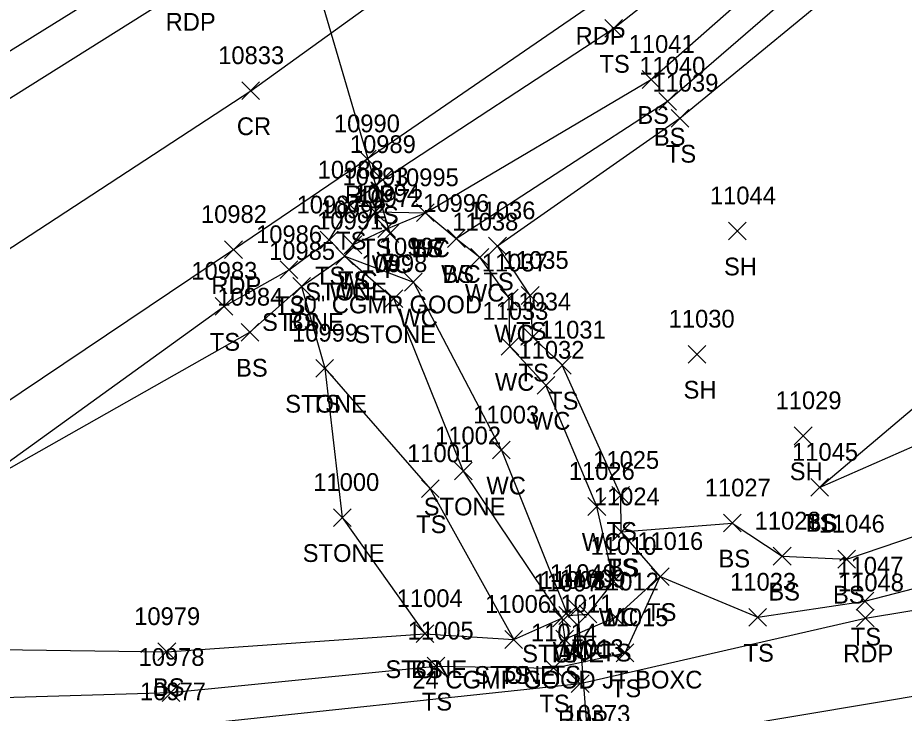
# Model space of a CAD drawing. Extents: x 1475671 to 1477951, y 592661 to 593821.
# Drawn here: x 1476588.2 to 1476688.2, y 593075.6 to 593153.9 of the extents above; entities that cross this region are included whole.
import ezdxf

# ---------------------------------------------------------------- set-up
doc = ezdxf.new("R2010")
doc.units = 0
for name, color, linetype in [('D_A', 7, 'Continuous'), ('D_C', 7, 'Continuous'), ('D_I', 7, 'Continuous'), ('D_TIC', 7, 'Continuous'), ('DCP', 7, 'Continuous'), ('L_A', 7, 'Continuous'), ('L_I', 7, 'Continuous'), ('L_TIC', 7, 'Continuous'), ('LASF', 7, 'Continuous'), ('LAWE', 7, 'Continuous'), ('LELB', 7, 'Continuous'), ('P_A', 7, 'Continuous'), ('P_I', 7, 'Continuous'), ('P_TIC', 7, 'Continuous'), ('PET', 7, 'Continuous'), ('PRC', 7, 'Continuous')]:
    doc.layers.add(name, color=color, linetype=linetype)

msp = doc.modelspace()

# ---------------------------------------------------------------- linework, layer by layer
at = {"layer": 'D_TIC'}
for points in [[(1476629.198, 593128.602), (1476631.198, 593130.602)], [(1476631.198, 593128.602), (1476629.198, 593130.602)], [(1476650.343, 593086.34), (1476652.343, 593088.34)], [(1476652.343, 593086.34), (1476650.343, 593088.34)]]:
    msp.add_lwpolyline(points, dxfattribs=at)
at = {"layer": 'DCP'}
for points in [[(1476616.882, 593174.886), (1476630.198, 593129.602)], [(1476651.343, 593087.34), (1476653.654, 593058.021)]]:
    msp.add_lwpolyline(points, dxfattribs=at)
at = {"layer": 'L_TIC'}
for points in [[(1476654.414, 593151.716), (1476656.414, 593153.716)], [(1476656.414, 593151.716), (1476654.414, 593153.716)], [(1476658.654, 593145.953), (1476660.654, 593147.953)], [(1476660.654, 593145.953), (1476658.654, 593147.953)], [(1476660.509, 593143.505), (1476662.509, 593145.505)], [(1476662.509, 593143.505), (1476660.509, 593145.505)], [(1476661.901, 593141.587), (1476663.901, 593143.587)], [(1476663.901, 593141.587), (1476661.901, 593143.587)], [(1476628.363, 593134.667), (1476630.363, 593136.667)], [(1476630.363, 593134.667), (1476628.363, 593136.667)], [(1476624.724, 593131.792), (1476626.724, 593133.792)], [(1476626.724, 593131.792), (1476624.724, 593133.792)], [(1476627.529, 593131.031), (1476629.529, 593133.031)], [(1476629.529, 593131.031), (1476627.529, 593133.031)], [(1476633.196, 593130.937), (1476635.196, 593132.937)], [(1476635.196, 593130.937), (1476633.196, 593132.937)], [(1476633.196, 593130.937), (1476635.196, 593132.937)], [(1476635.196, 593130.937), (1476633.196, 593132.937)], [(1476633.196, 593130.937), (1476635.196, 593132.937)], [(1476635.196, 593130.937), (1476633.196, 593132.937)], [(1476628.839, 593129.141), (1476630.839, 593131.141)], [(1476630.839, 593129.141), (1476628.839, 593131.141)], [(1476668.378, 593128.885), (1476670.378, 593130.885)], [(1476670.378, 593128.885), (1476668.378, 593130.885)], [(1476622.348, 593127.862), (1476624.348, 593129.862)], [(1476624.348, 593127.862), (1476622.348, 593129.862)], [(1476625.038, 593127.324), (1476627.038, 593129.324)], [(1476627.038, 593127.324), (1476625.038, 593129.324)], [(1476625.038, 593127.324), (1476627.038, 593129.324)], [(1476627.038, 593127.324), (1476625.038, 593129.324)], [(1476636.677, 593128.038), (1476638.677, 593130.038)], [(1476638.677, 593128.038), (1476636.677, 593130.038)], [(1476636.677, 593128.038), (1476638.677, 593130.038)], [(1476638.677, 593128.038), (1476636.677, 593130.038)], [(1476641.326, 593127.206), (1476643.326, 593129.206)], [(1476643.326, 593127.206), (1476641.326, 593129.206)], [(1476624.1, 593126.06), (1476626.1, 593128.06)], [(1476626.1, 593126.06), (1476624.1, 593128.06)], [(1476624.1, 593126.06), (1476626.1, 593128.06)], [(1476626.1, 593126.06), (1476624.1, 593128.06)], [(1476624.1, 593126.06), (1476626.1, 593128.06)], [(1476626.1, 593126.06), (1476624.1, 593128.06)], [(1476639.338, 593125.932), (1476641.338, 593127.932)], [(1476641.338, 593125.932), (1476639.338, 593127.932)], [(1476639.338, 593125.932), (1476641.338, 593127.932)], [(1476641.338, 593125.932), (1476639.338, 593127.932)], [(1476617.836, 593124.518), (1476619.836, 593126.518)], [(1476619.836, 593124.518), (1476617.836, 593126.518)], [(1476619.244, 593122.636), (1476621.244, 593124.636)], [(1476621.244, 593122.636), (1476619.244, 593124.636)], [(1476619.244, 593122.636), (1476621.244, 593124.636)], [(1476621.244, 593122.636), (1476619.244, 593124.636)], [(1476619.244, 593122.636), (1476621.244, 593124.636)], [(1476621.244, 593122.636), (1476619.244, 593124.636)], [(1476631.844, 593123.124), (1476633.844, 593125.124)], [(1476633.844, 593123.124), (1476631.844, 593125.124)], [(1476629.644, 593121.248), (1476631.644, 593123.248)], [(1476631.644, 593121.248), (1476629.644, 593123.248)], [(1476642.649, 593121.325), (1476644.649, 593123.325)], [(1476644.649, 593121.325), (1476642.649, 593123.325)], [(1476645.015, 593121.62), (1476647.015, 593123.62)], [(1476647.015, 593121.62), (1476645.015, 593123.62)], [(1476610.484, 593120.393), (1476612.484, 593122.393)], [(1476612.484, 593120.393), (1476610.484, 593122.393)], [(1476613.413, 593117.476), (1476615.413, 593119.476)], [(1476615.413, 593117.476), (1476613.413, 593119.476)], [(1476645.295, 593116.931), (1476647.295, 593118.931)], [(1476647.295, 593116.931), (1476645.295, 593118.931)], [(1476642.724, 593115.881), (1476644.724, 593117.881)], [(1476644.724, 593115.881), (1476642.724, 593117.881)], [(1476663.813, 593115.002), (1476665.813, 593117.002)], [(1476665.813, 593115.002), (1476663.813, 593117.002)], [(1476621.849, 593113.421), (1476623.849, 593115.421)], [(1476623.849, 593113.421), (1476621.849, 593115.421)], [(1476621.849, 593113.421), (1476623.849, 593115.421)], [(1476623.849, 593113.421), (1476621.849, 593115.421)], [(1476648.631, 593113.766), (1476650.631, 593115.766)], [(1476650.631, 593113.766), (1476648.631, 593115.766)], [(1476646.792, 593111.499), (1476648.792, 593113.499)], [(1476648.792, 593111.499), (1476646.792, 593113.499)], [(1476675.786, 593105.811), (1476677.786, 593107.811)], [(1476677.786, 593105.811), (1476675.786, 593107.811)], [(1476641.768, 593104.199), (1476643.768, 593106.199)], [(1476643.768, 593104.199), (1476641.768, 593106.199)], [(1476637.472, 593101.841), (1476639.472, 593103.841)], [(1476639.472, 593101.841), (1476637.472, 593103.841)], [(1476633.755, 593099.845), (1476635.755, 593101.845)], [(1476635.755, 593099.845), (1476633.755, 593101.845)], [(1476677.643, 593099.996), (1476679.643, 593101.996)], [(1476679.643, 593099.996), (1476677.643, 593101.996)], [(1476677.643, 593099.996), (1476679.643, 593101.996)], [(1476679.643, 593099.996), (1476677.643, 593101.996)], [(1476655.219, 593099.091), (1476657.219, 593101.091)], [(1476657.219, 593099.091), (1476655.219, 593101.091)], [(1476655.219, 593099.091), (1476657.219, 593101.091)], [(1476657.219, 593099.091), (1476655.219, 593101.091)], [(1476652.527, 593097.843), (1476654.527, 593099.843)], [(1476654.527, 593097.843), (1476652.527, 593099.843)], [(1476623.828, 593096.599), (1476625.828, 593098.599)], [(1476625.828, 593096.599), (1476623.828, 593098.599)], [(1476667.799, 593095.978), (1476669.799, 593097.978)], [(1476669.799, 593095.978), (1476667.799, 593097.978)], [(1476655.284, 593094.976), (1476657.284, 593096.976)], [(1476657.284, 593094.976), (1476655.284, 593096.976)], [(1476655.284, 593094.976), (1476657.284, 593096.976)], [(1476657.284, 593094.976), (1476655.284, 593096.976)], [(1476673.422, 593092.252), (1476675.422, 593094.252)], [(1476675.422, 593092.252), (1476673.422, 593094.252)], [(1476680.706, 593091.914), (1476682.706, 593093.914)], [(1476682.706, 593091.914), (1476680.706, 593093.914)], [(1476654.436, 593089.406), (1476656.436, 593091.406)], [(1476656.436, 593089.406), (1476654.436, 593091.406)], [(1476659.671, 593089.953), (1476661.671, 593091.953)], [(1476661.671, 593089.953), (1476659.671, 593091.953)], [(1476659.671, 593089.953), (1476661.671, 593091.953)], [(1476661.671, 593089.953), (1476659.671, 593091.953)], [(1476682.751, 593087.182), (1476684.751, 593089.182)], [(1476684.751, 593087.182), (1476682.751, 593089.182)], [(1476648.567, 593085.274), (1476650.567, 593087.274)], [(1476650.567, 593085.274), (1476648.567, 593087.274)], [(1476648.567, 593085.274), (1476650.567, 593087.274)], [(1476650.567, 593085.274), (1476648.567, 593087.274)], [(1476648.567, 593085.274), (1476650.567, 593087.274)], [(1476650.567, 593085.274), (1476648.567, 593087.274)], [(1476649.26, 593085.567), (1476651.26, 593087.567)], [(1476651.26, 593085.567), (1476649.26, 593087.567)], [(1476651.52, 593085.726), (1476653.52, 593087.726)], [(1476653.52, 593085.726), (1476651.52, 593087.726)], [(1476654.619, 593085.384), (1476656.619, 593087.384)], [(1476656.619, 593085.384), (1476654.619, 593087.384)], [(1476670.661, 593085.365), (1476672.661, 593087.365)], [(1476672.661, 593085.365), (1476670.661, 593087.365)], [(1476633.151, 593083.513), (1476635.151, 593085.513)], [(1476635.151, 593083.513), (1476633.151, 593085.513)], [(1476633.151, 593083.513), (1476635.151, 593085.513)], [(1476635.151, 593083.513), (1476633.151, 593085.513)], [(1476643.161, 593082.865), (1476645.161, 593084.865)], [(1476645.161, 593082.865), (1476643.161, 593084.865)], [(1476643.161, 593082.865), (1476645.161, 593084.865)], [(1476645.161, 593082.865), (1476643.161, 593084.865)], [(1476648.912, 593082.903), (1476650.912, 593084.903)], [(1476650.912, 593082.903), (1476648.912, 593084.903)], [(1476604.047, 593081.486), (1476606.047, 593083.486)], [(1476606.047, 593081.486), (1476604.047, 593083.486)], [(1476655.704, 593081.361), (1476657.704, 593083.361)], [(1476657.704, 593081.361), (1476655.704, 593083.361)], [(1476634.384, 593079.856), (1476636.384, 593081.856)], [(1476636.384, 593079.856), (1476634.384, 593081.856)], [(1476647.642, 593079.648), (1476649.642, 593081.648)], [(1476649.642, 593079.648), (1476647.642, 593081.648)], [(1476604.53, 593076.889), (1476606.53, 593078.889)], [(1476606.53, 593076.889), (1476604.53, 593078.889)]]:
    msp.add_lwpolyline(points, dxfattribs=at)
at = {"layer": 'LASF'}
for points in [[(1476620.244, 593123.636), (1476625.1, 593127.06), (1476630.644, 593122.248), (1476638.472, 593102.841), (1476649.567, 593086.274)], [(1476620.244, 593123.636), (1476622.849, 593114.421), (1476624.828, 593097.599), (1476634.151, 593084.513), (1476644.161, 593083.865), (1476649.567, 593086.274)]]:
    msp.add_lwpolyline(points, dxfattribs=at)
at = {"layer": 'LAWE'}
for points in [[(1476625.1, 593127.06), (1476626.038, 593128.324), (1476629.839, 593130.141), (1476634.196, 593131.937), (1476637.677, 593129.038), (1476640.338, 593126.932)], [(1476625.1, 593127.06), (1476632.844, 593124.124), (1476642.768, 593105.199), (1476650.26, 593086.567), (1476652.52, 593086.726), (1476655.436, 593090.406), (1476653.527, 593098.843), (1476647.792, 593112.499), (1476643.724, 593116.881), (1476643.649, 593122.325), (1476640.338, 593126.932)]]:
    msp.add_lwpolyline(points, dxfattribs=at)
at = {"layer": 'LELB'}
for points in [[(1476525.71, 593116.601), (1476535.993, 593117.469), (1476564.386, 593135.958), (1476604.974, 593161.161), (1476624.83, 593173.855), (1476638.095, 593183.34), (1476660.789, 593199.46), (1476676.812, 593212.322), (1476707.127, 593238.69), (1476723.806, 593252.602), (1476754.144, 593278.445), (1476785.314, 593303.015), (1476812.795, 593326.193), (1476842.986, 593352.592), (1476863.072, 593369.432), (1476886.56, 593389.771), (1476893.658, 593396.85), (1476901.202, 593401.682), (1476921.171, 593422.2)], [(1476564.119, 593090.41), (1476582.109, 593100.232), (1476611.484, 593121.393), (1476618.836, 593125.518), (1476623.348, 593128.862), (1476625.724, 593132.792), (1476629.363, 593135.667), (1476655.414, 593152.716), (1476679.208, 593171.494), (1476707.001, 593193.967), (1476724.55, 593208.697), (1476750.977, 593231.694), (1476770.543, 593248.256), (1476798.665, 593272.173), (1476825.817, 593296.201), (1476846.601, 593313.128), (1476851.351, 593312.899), (1476856.135, 593310.718)], [(1476634.196, 593131.937), (1476659.654, 593146.953), (1476682.124, 593166.734), (1476708.671, 593192.239), (1476725.714, 593207.355), (1476752.229, 593229.936), (1476771.816, 593246.254), (1476799.288, 593271.002), (1476827.809, 593293.853), (1476847.078, 593308.339), (1476849.309, 593306.853)], [(1476637.677, 593129.038), (1476661.509, 593144.505), (1476683.495, 593163.513), (1476710.241, 593189.501), (1476727.499, 593204.939), (1476753.67, 593228.482), (1476773.331, 593243.799), (1476800.693, 593269.416), (1476829.365, 593291.343), (1476849.309, 593306.853)], [(1476656.284, 593095.976), (1476668.799, 593096.978), (1476674.422, 593093.252), (1476681.706, 593092.914), (1476715.012, 593104.198), (1476743.407, 593111.461), (1476771.495, 593107.276), (1476782.768, 593105.348), (1476795.281, 593099.965), (1476811.259, 593100.054), (1476809.565, 593119.113), (1476813.359, 593153.775), (1476804.907, 593159.056), (1476804.556, 593163.805), (1476803.63, 593168.615), (1476810.963, 593186.977), (1476819.408, 593209.797), (1476828.138, 593245.308), (1476843.633, 593278.61), (1476845.713, 593295.921), (1476849.309, 593306.853)], [(1476678.643, 593100.996), (1476705.615, 593123.798), (1476726.041, 593155.108), (1476737.723, 593186.361), (1476761.68, 593213.282), (1476787.873, 593223.87), (1476810.461, 593252.94), (1476833.913, 593283.757), (1476845.713, 593295.921)], [(1476656.219, 593100.091), (1476649.631, 593114.766), (1476646.295, 593117.931), (1476646.015, 593122.62), (1476642.326, 593128.206), (1476662.901, 593142.587), (1476684.96, 593160.732), (1476712.646, 593184.752), (1476728.902, 593202.646), (1476756.289, 593223.253), (1476776.283, 593240.544), (1476803.274, 593265.829), (1476831.654, 593287.608)], [(1476678.643, 593100.996), (1476711.001, 593115.173), (1476731.223, 593143.421), (1476747.615, 593171.009), (1476767.456, 593198.639), (1476796.546, 593210.231), (1476815.094, 593241.804), (1476843.633, 593278.61)], [(1476626.038, 593128.324), (1476628.529, 593132.031), (1476634.196, 593131.937)], [(1476582.109, 593100.232), (1476614.413, 593118.476), (1476620.244, 593123.636)], [(1476622.849, 593114.421), (1476634.755, 593100.845), (1476644.161, 593083.865)], [(1476564.119, 593090.41), (1476564.346, 593083.027), (1476564.937, 593076.683), (1476605.53, 593077.889), (1476635.384, 593080.856), (1476648.642, 593080.648), (1476656.704, 593082.361), (1476660.671, 593090.953), (1476671.661, 593086.365), (1476683.751, 593088.182), (1476716.338, 593096.606), (1476747.988, 593101.226)], [(1476649.567, 593086.274), (1476649.912, 593083.903), (1476655.619, 593086.384), (1476660.671, 593090.953), (1476656.284, 593095.976), (1476656.219, 593100.091)], [(1476564.346, 593083.027), (1476605.047, 593082.486), (1476634.151, 593084.513)]]:
    msp.add_lwpolyline(points, dxfattribs=at)
at = {"layer": 'P_TIC'}
for points in [[(1476613.511, 593144.687), (1476615.511, 593146.687)], [(1476615.511, 593144.687), (1476613.511, 593146.687)], [(1476626.642, 593137.007), (1476628.642, 593139.007)], [(1476628.642, 593137.007), (1476626.642, 593139.007)], [(1476611.568, 593126.792), (1476613.568, 593128.792)], [(1476613.568, 593126.792), (1476611.568, 593128.792)], [(1476682.811, 593085.28), (1476684.811, 593087.28)], [(1476684.811, 593085.28), (1476682.811, 593087.28)], [(1476650.648, 593077.887), (1476652.648, 593079.887)], [(1476652.648, 593077.887), (1476650.648, 593079.887)]]:
    msp.add_lwpolyline(points, dxfattribs=at)
at = {"layer": 'PET'}
for points in [[(1476493.608, 593061.898), (1476518.902, 593073.258), (1476550.122, 593088.216), (1476579.1, 593105.347), (1476612.568, 593127.792), (1476627.642, 593138.007), (1476653.647, 593155.862), (1476677.366, 593174.623), (1476705.428, 593196.668), (1476722.658, 593210.687), (1476749.608, 593233.446), (1476768.814, 593249.961), (1476797.5, 593274.025), (1476824.823, 593297.545), (1476844.998, 593315.289), (1476868.192, 593333.861), (1476888.665, 593352.984), (1476918.008, 593376.949), (1476944.228, 593398.872), (1476967.732, 593418.704), (1476998.53, 593444.473)], [(1476459.251, 593078.48), (1476508.394, 593100.167), (1476518.15, 593105.127), (1476565.375, 593131.075), (1476607.427, 593157.454), (1476640.246, 593180.542), (1476678.206, 593210.569), (1476708.642, 593235.747), (1476725.67, 593249.833), (1476755.845, 593275.302), (1476786.304, 593300.734), (1476814.322, 593324.283), (1476845.049, 593350.022), (1476865.022, 593366.821), (1476897.041, 593395.14), (1476922.982, 593419.08), (1476952.357, 593443.372)], [(1476550.122, 593088.216), (1476546.989, 593080.789), (1476546.616, 593074.303), (1476558.015, 593070.453), (1476566.603, 593070.835), (1476605.696, 593074.016), (1476651.648, 593078.887), (1476683.811, 593086.28), (1476716.781, 593091.72), (1476756.304, 593096.319), (1476786.758, 593094.615), (1476795.521, 593092.664), (1476816.876, 593085.292), (1476835.432, 593074.221), (1476828.621, 593102.019), (1476824.417, 593119.747), (1476821.585, 593140.768), (1476821.023, 593163.56), (1476821.925, 593180.441), (1476827.117, 593207.843), (1476837.471, 593243.387), (1476848.828, 593278.298), (1476858.441, 593303.191), (1476868.192, 593333.861)]]:
    msp.add_lwpolyline(points, dxfattribs=at)
at = {"layer": 'PRC'}
for points in [[(1476461.982, 593064.616), (1476520.699, 593090.525), (1476540.789, 593101.338), (1476577.672, 593121.61), (1476614.511, 593145.687), (1476649.358, 593170.811), (1476687.024, 593200.014), (1476716.688, 593224.246), (1476733.583, 593238.31), (1476760.901, 593261.207), (1476795.35, 593290.137), (1476823.06, 593313.512), (1476854.069, 593339.52), (1476875.702, 593357.51), (1476907.008, 593384.083), (1476934.059, 593407.682), (1476963.455, 593432.806)], [(1476783.703, 593084.944), (1476761.584, 593086.675), (1476734.111, 593084.661), (1476691.896, 593077.875), (1476653.536, 593071.485), (1476592.217, 593062.913), (1476555.355, 593059.5), (1476520.454, 593058.112), (1476501.288, 593059.515), (1476493.608, 593061.898)]]:
    msp.add_lwpolyline(points, dxfattribs=at)

# ---------------------------------------------------------------- texts
at = {"layer": 'D_A'}
for p in [(1476629.576, 593124.602), (1476650.721, 593082.34)]:
    msp.add_text('P', height=2, dxfattribs=at).set_placement(p)
at = {"layer": 'D_C'}
for s, p in [('30" CGMP GOOD', (1476618.978, 593120.602)), ('24 CGMP GOOD JT BOXC', (1476632.737, 593078.34))]:
    msp.add_text(s, height=2, dxfattribs=at).set_placement(p)
at = {"layer": 'D_I'}
for s, p in [('10972', (1476626.529, 593132.602)), ('11049', (1476648.233, 593090.34))]:
    msp.add_text(s, height=2, dxfattribs=at).set_placement(p)
at = {"layer": 'L_A'}
for s, p in [('TS', (1476653.824, 593147.716)), ('BS', (1476658.095, 593141.953)), ('BS', (1476659.95, 593139.505)), ('TS', (1476661.31, 593137.587)), ('TS', (1476627.772, 593130.667)), ('TS', (1476624.133, 593127.792)), ('TS', (1476626.938, 593127.031)), ('WC', (1476632.503, 593126.937)), ('TS', (1476632.606, 593126.937)), ('BS', (1476632.637, 593126.937)), ('WC', (1476628.146, 593125.141)), ('SH', (1476667.866, 593124.885)), ('TS', (1476621.757, 593123.862)), ('WC', (1476624.346, 593123.324)), ('TS', (1476624.448, 593123.324)), ('WC', (1476635.984, 593124.038)), ('BS', (1476636.118, 593124.038)), ('TS', (1476640.735, 593123.206)), ('STONE', (1476620.643, 593122.06)), ('WC', (1476623.407, 593122.06)), ('WC', (1476623.407, 593122.06)), ('WC', (1476638.645, 593121.932)), ('WC', (1476638.645, 593121.932)), ('TS', (1476617.245, 593120.518)), ('WC', (1476631.151, 593119.124)), ('STONE', (1476615.788, 593118.636)), ('STONE', (1476615.788, 593118.636)), ('BS', (1476618.685, 593118.636)), ('STONE', (1476626.187, 593117.248)), ('WC', (1476641.957, 593117.325)), ('TS', (1476644.424, 593117.62)), ('TS', (1476609.894, 593116.393)), ('BS', (1476612.854, 593113.476)), ('TS', (1476644.705, 593112.931)), ('WC', (1476642.032, 593111.881)), ('SH', (1476663.302, 593111.002)), ('STONE', (1476618.392, 593109.421)), ('TS', (1476621.259, 593109.421)), ('TS', (1476648.04, 593109.766)), ('WC', (1476646.099, 593107.499)), ('SH', (1476675.275, 593101.811)), ('WC', (1476641.075, 593100.199)), ('STONE', (1476634.015, 593097.841)), ('TS', (1476633.165, 593095.845)), ('TS', (1476677.053, 593095.996)), ('BS', (1476677.084, 593095.996)), ('TS', (1476654.629, 593095.091)), ('TS', (1476654.629, 593095.091)), ('WC', (1476651.834, 593093.843)), ('STONE', (1476620.371, 593092.599)), ('BS', (1476667.24, 593091.978)), ('TS', (1476654.693, 593090.976)), ('BS', (1476654.725, 593090.976)), ('BS', (1476672.863, 593088.252)), ('BS', (1476680.147, 593087.914)), ('WC', (1476653.743, 593085.406)), ('TS', (1476659.081, 593085.953)), ('TS', (1476659.081, 593085.953)), ('TS', (1476682.16, 593083.182)), ('STONE', (1476645.11, 593081.274)), ('STONE', (1476645.11, 593081.274)), ('TS', (1476647.976, 593081.274)), ('WC', (1476648.567, 593081.567)), ('WC', (1476650.827, 593081.726)), ('TS', (1476654.029, 593081.384)), ('TS', (1476670.07, 593081.365)), ('STONE', (1476629.695, 593079.513)), ('BS', (1476632.592, 593079.513)), ('STONE', (1476639.704, 593078.865)), ('TS', (1476642.57, 593078.865)), ('TS', (1476648.321, 593078.903)), ('BS', (1476603.488, 593077.486)), ('TS', (1476655.114, 593077.361)), ('TS', (1476633.793, 593075.856)), ('TS', (1476647.052, 593075.648))]:
    msp.add_text(s, height=2, dxfattribs=at).set_placement(p)
at = {"layer": 'L_I'}
for s, p in [('11041', (1476657.119, 593149.953)), ('11040', (1476658.32, 593147.505)), ('11039', (1476659.791, 593145.587)), ('10989', (1476625.686, 593138.667)), ('10988', (1476622.055, 593135.792)), ('10993', (1476624.86, 593135.031)), ('10995', (1476630.527, 593134.937)), ('10995', (1476630.527, 593134.937)), ('10995', (1476630.527, 593134.937)), ('10994', (1476626.169, 593133.141)), ('11044', (1476666.275, 593132.885)), ('10987', (1476619.678, 593131.862)), ('10992', (1476622.369, 593131.324)), ('10992', (1476622.369, 593131.324)), ('10996', (1476633.953, 593132.038)), ('10996', (1476633.953, 593132.038)), ('11036', (1476639.168, 593131.206)), ('10991', (1476621.998, 593130.06)), ('10991', (1476621.998, 593130.06)), ('10991', (1476621.998, 593130.06)), ('11038', (1476637.236, 593129.932)), ('11038', (1476637.236, 593129.932)), ('10986', (1476615.111, 593128.518)), ('10997', (1476629.175, 593127.124)), ('10985', (1476616.575, 593126.636)), ('10985', (1476616.575, 593126.636)), ('10985', (1476616.575, 593126.636)), ('10998', (1476626.975, 593125.248)), ('11037', (1476640.547, 593125.325)), ('11035', (1476642.912, 593125.62)), ('10983', (1476607.815, 593124.393)), ('10984', (1476610.744, 593121.476)), ('11034', (1476643.193, 593120.931)), ('11033', (1476640.622, 593119.881)), ('11030', (1476661.624, 593119.002)), ('10999', (1476619.172, 593117.421)), ('10999', (1476619.172, 593117.421)), ('11031', (1476647.095, 593117.766)), ('11032', (1476644.69, 593115.499)), ('11029', (1476673.676, 593109.811)), ('11003', (1476639.587, 593108.199)), ('11002', (1476635.291, 593105.841)), ('11001', (1476632.141, 593103.845)), ('11045', (1476675.541, 593103.996)), ('11045', (1476675.541, 593103.996)), ('11025', (1476653.117, 593103.091)), ('11025', (1476653.117, 593103.091)), ('11026', (1476650.369, 593101.843)), ('11000', (1476621.56, 593100.599)), ('11027', (1476665.696, 593099.978)), ('11024', (1476653.182, 593098.976)), ('11024', (1476653.182, 593098.976)), ('11028', (1476671.32, 593096.252)), ('11046', (1476678.549, 593095.914)), ('11010', (1476652.814, 593093.406)), ('11016', (1476658.081, 593093.953)), ('11016', (1476658.081, 593093.953)), ('11047', (1476680.648, 593091.182)), ('11007', (1476646.386, 593089.274)), ('11007', (1476646.386, 593089.274)), ('11007', (1476646.386, 593089.274)), ('11008', (1476647.079, 593089.567)), ('11009', (1476649.331, 593089.726)), ('11012', (1476653.084, 593089.384)), ('11023', (1476668.558, 593089.365)), ('11004', (1476630.97, 593087.513)), ('11004', (1476630.97, 593087.513)), ('11006', (1476640.924, 593086.865)), ('11006', (1476640.924, 593086.865)), ('11011', (1476647.943, 593086.903)), ('10979', (1476601.37, 593085.486)), ('11015', (1476654.169, 593085.361)), ('11005', (1476632.203, 593083.856)), ('11014', (1476646.107, 593083.648)), ('10978', (1476601.861, 593080.889))]:
    msp.add_text(s, height=2, dxfattribs=at).set_placement(p)
at = {"layer": 'P_A'}
for s, p in [('RDP', (1476604.915, 593152.454)), ('RDP', (1476651.135, 593150.862)), ('CR', (1476612.944, 593140.687)), ('RDP', (1476625.13, 593133.007)), ('RDP', (1476610.056, 593122.792)), ('RDP', (1476681.299, 593081.28)), ('RDP', (1476649.137, 593073.887))]:
    msp.add_text(s, height=2, dxfattribs=at).set_placement(p)
at = {"layer": 'P_I'}
for s, p in [('10833', (1476610.842, 593148.687)), ('10990', (1476623.886, 593141.007)), ('10982', (1476608.898, 593130.792)), ('11048', (1476680.709, 593089.28)), ('11013', (1476649.113, 593081.887)), ('10977', (1476602.027, 593077.016)), ('10373', (1476649.867, 593074.485))]:
    msp.add_text(s, height=2, dxfattribs=at).set_placement(p)

doc.saveas('drawing.dxf')
